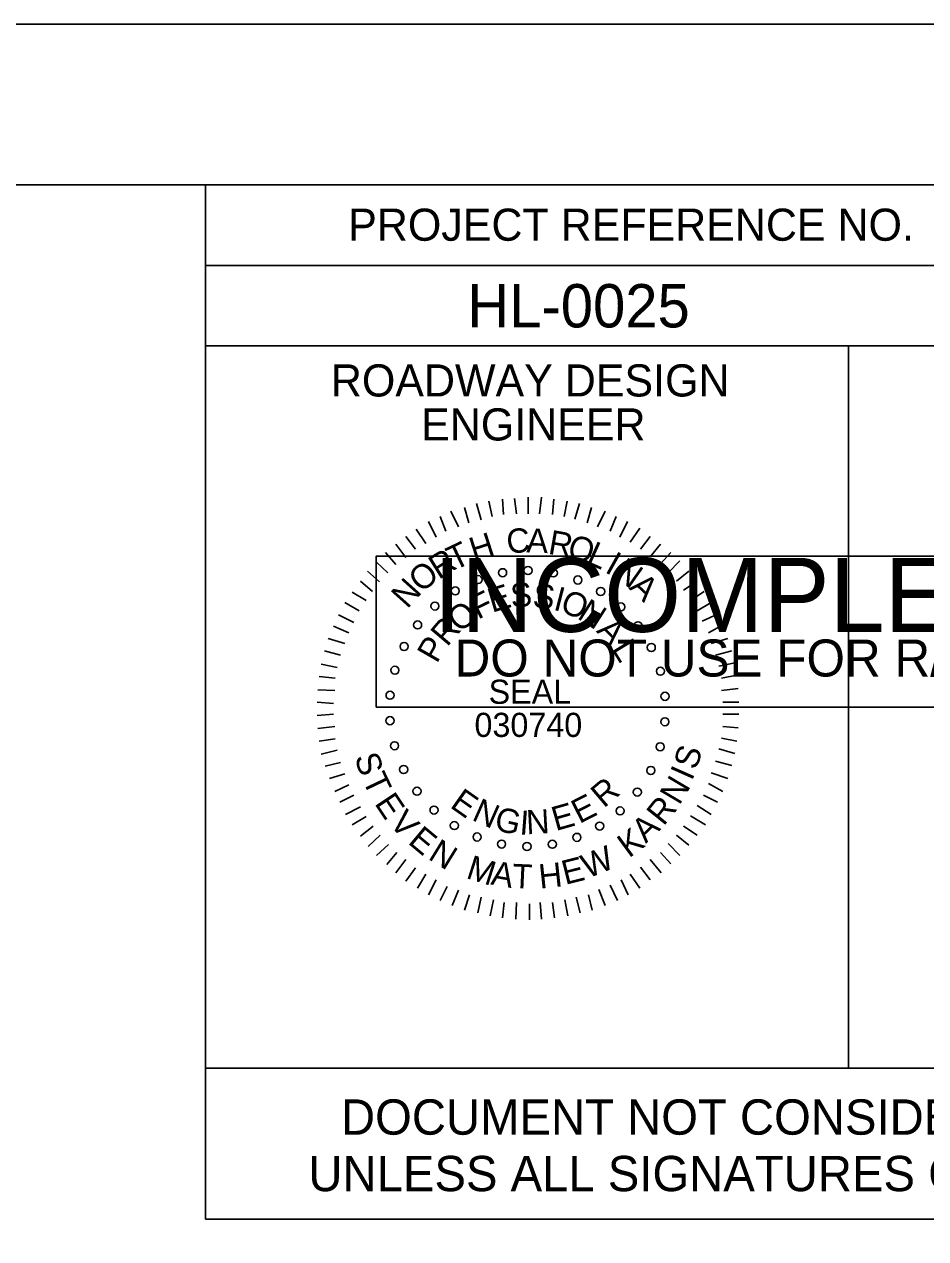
# Model space of a CAD drawing. Extents: x 1487909 to 1489267, y 497866 to 499814.
# Drawn here: x 1489027.14 to 1489041.17, y 497957.31 to 497976.22 of the extents above; entities that cross this region are included whole.
import ezdxf

# ---------------------------------------------------------------- set-up
doc = ezdxf.new("R2010")
doc.units = 0
for name, color, linetype in [('Old_Level_9', 7, 'Continuous'), ('Sheet Data Field CELL', 7, 'Continuous'), ('Sheet Plot Border Outside CELL', 7, 'Continuous'), ('Sheet Sticker Exception Certification CELL', 7, 'Continuous'), ('Sheet Sticker Incomplete CELL', 7, 'Continuous'), ('Sheet Typical CELL', 7, 'Continuous')]:
    doc.layers.add(name, color=color, linetype=linetype)

msp = doc.modelspace()

# ---------------------------------------------------------------- linework, layer by layer
at = {"layer": 'Old_Level_9'}
for p, q in [((1489034.178, 497968.758), (1489034.248, 497968.508)), ((1489034.368, 497968.798), (1489034.418, 497968.558)), ((1489034.578, 497968.828), (1489034.598, 497968.588)), ((1489034.768, 497968.838), (1489034.798, 497968.598)), ((1489034.978, 497968.858), (1489034.978, 497968.598)), ((1489035.188, 497968.858), (1489035.158, 497968.598)), ((1489035.378, 497968.828), (1489035.358, 497968.588)), ((1489035.588, 497968.798), (1489035.538, 497968.558)), ((1489035.778, 497968.758), (1489035.708, 497968.518)), ((1489033.608, 497968.558), (1489033.698, 497968.328)), ((1489033.778, 497968.638), (1489033.898, 497968.398)), ((1489033.988, 497968.698), (1489034.058, 497968.458)), ((1489035.968, 497968.698), (1489035.898, 497968.458)), ((1489036.178, 497968.638), (1489036.058, 497968.398)), ((1489036.348, 497968.558), (1489036.258, 497968.328)), ((1489033.428, 497968.478), (1489033.548, 497968.238)), ((1489036.528, 497968.478), (1489036.408, 497968.238)), ((1489036.718, 497968.378), (1489036.568, 497968.158)), ((1489033.078, 497968.248), (1489033.228, 497968.048)), ((1489033.238, 497968.358), (1489033.388, 497968.138)), ((1489036.878, 497968.248), (1489036.728, 497968.048)), ((1489032.758, 497967.998), (1489032.918, 497967.808)), ((1489032.918, 497968.128), (1489033.078, 497967.918)), ((1489037.038, 497968.128), (1489036.878, 497967.928)), ((1489037.198, 497967.998), (1489037.038, 497967.818)), ((1489032.618, 497967.848), (1489032.798, 497967.678)), ((1489037.338, 497967.868), (1489037.158, 497967.678)), ((1489032.478, 497967.708), (1489032.668, 497967.538)), ((1489037.478, 497967.708), (1489037.288, 497967.548)), ((1489032.368, 497967.548), (1489032.558, 497967.388)), ((1489037.608, 497967.548), (1489037.398, 497967.408)), ((1489032.238, 497967.378), (1489032.458, 497967.248)), ((1489037.718, 497967.388), (1489037.508, 497967.248)), ((1489032.128, 497967.218), (1489032.348, 497967.088)), ((1489037.828, 497967.218), (1489037.608, 497967.088)), ((1489037.928, 497967.038), (1489037.688, 497966.928)), ((1489032.028, 497967.028), (1489032.268, 497966.908)), ((1489038.008, 497966.868), (1489037.788, 497966.748)), ((1489031.948, 497966.848), (1489032.188, 497966.748)), ((1489031.868, 497966.658), (1489032.128, 497966.578)), ((1489038.088, 497966.658), (1489037.828, 497966.578)), ((1489031.808, 497966.468), (1489032.058, 497966.398)), ((1489038.148, 497966.468), (1489037.898, 497966.398)), ((1489031.758, 497966.258), (1489032.008, 497966.208)), ((1489038.198, 497966.278), (1489037.948, 497966.228)), ((1489031.728, 497966.068), (1489031.978, 497966.038)), ((1489038.228, 497966.088), (1489037.988, 497966.038)), ((1489031.708, 497965.858), (1489031.968, 497965.848)), ((1489038.248, 497965.878), (1489037.988, 497965.848)), ((1489031.698, 497965.668), (1489031.948, 497965.648)), ((1489038.258, 497965.668), (1489038.008, 497965.668)), ((1489031.698, 497965.458), (1489031.948, 497965.478)), ((1489038.258, 497965.478), (1489038.008, 497965.478)), ((1489031.708, 497965.258), (1489031.968, 497965.288)), ((1489038.248, 497965.268), (1489038.008, 497965.288)), ((1489031.728, 497965.058), (1489031.978, 497965.098)), ((1489038.228, 497965.058), (1489037.988, 497965.108)), ((1489031.758, 497964.858), (1489032.008, 497964.918)), ((1489038.198, 497964.868), (1489037.948, 497964.938)), ((1489031.818, 497964.668), (1489032.058, 497964.728)), ((1489038.148, 497964.678), (1489037.898, 497964.748)), ((1489031.888, 497964.478), (1489032.128, 497964.548)), ((1489038.008, 497964.278), (1489037.788, 497964.398)), ((1489038.088, 497964.478), (1489037.828, 497964.568)), ((1489031.968, 497964.278), (1489032.188, 497964.378)), ((1489032.048, 497964.108), (1489032.268, 497964.218)), ((1489037.928, 497964.108), (1489037.708, 497964.218)), ((1489032.138, 497963.918), (1489032.368, 497964.038)), ((1489037.828, 497963.918), (1489037.608, 497964.058)), ((1489032.238, 497963.758), (1489032.458, 497963.888)), ((1489037.738, 497963.758), (1489037.508, 497963.898)), ((1489032.368, 497963.578), (1489032.568, 497963.738)), ((1489037.608, 497963.598), (1489037.398, 497963.738)), ((1489032.488, 497963.418), (1489032.678, 497963.598)), ((1489032.618, 497963.278), (1489032.808, 497963.448)), ((1489037.338, 497963.278), (1489037.158, 497963.468)), ((1489037.478, 497963.438), (1489037.288, 497963.598)), ((1489032.778, 497963.138), (1489032.938, 497963.328)), ((1489037.198, 497963.148), (1489037.038, 497963.328)), ((1489032.918, 497963.008), (1489033.078, 497963.218)), ((1489033.078, 497962.878), (1489033.228, 497963.088)), ((1489036.878, 497962.898), (1489036.728, 497963.098)), ((1489037.048, 497963.008), (1489036.878, 497963.218)), ((1489033.258, 497962.768), (1489033.388, 497962.988)), ((1489033.428, 497962.668), (1489033.548, 497962.898)), ((1489036.538, 497962.668), (1489036.428, 497962.898)), ((1489036.718, 497962.768), (1489036.568, 497962.988)), ((1489033.608, 497962.578), (1489033.718, 497962.798)), ((1489033.798, 497962.498), (1489033.898, 497962.738)), ((1489036.178, 497962.498), (1489036.078, 497962.748)), ((1489036.368, 497962.578), (1489036.258, 497962.818)), ((1489033.988, 497962.428), (1489034.068, 497962.668)), ((1489034.198, 497962.388), (1489034.248, 497962.628)), ((1489034.388, 497962.338), (1489034.438, 497962.588)), ((1489034.578, 497962.308), (1489034.608, 497962.548)), ((1489034.788, 497962.288), (1489034.798, 497962.548)), ((1489034.998, 497962.278), (1489034.998, 497962.528)), ((1489035.188, 497962.288), (1489035.168, 497962.548)), ((1489035.388, 497962.308), (1489035.358, 497962.548)), ((1489035.598, 497962.338), (1489035.548, 497962.588)), ((1489035.788, 497962.388), (1489035.728, 497962.628)), ((1489035.978, 497962.428), (1489035.918, 497962.668))]:
    msp.add_line(p, q, dxfattribs=at)
for centre in [(1489034.201, 497967.575), (1489034.582, 497967.682), (1489034.977, 497967.717), (1489035.372, 497967.679), (1489035.753, 497967.569), (1489033.845, 497967.399), (1489036.108, 497967.39), (1489033.528, 497967.162), (1489036.423, 497967.15), (1489033.259, 497966.869), (1489036.689, 497966.856), (1489033.049, 497966.533), (1489036.896, 497966.518), (1489032.905, 497966.164), (1489037.038, 497966.148), (1489032.83, 497965.774), (1489037.11, 497965.758), (1489032.829, 497965.378), (1489037.108, 497965.361), (1489032.9, 497964.988), (1489037.034, 497964.972), (1489033.042, 497964.618), (1489036.889, 497964.603), (1489033.249, 497964.28), (1489036.679, 497964.266), (1489033.515, 497963.986), (1489036.411, 497963.974), (1489033.831, 497963.745), (1489036.093, 497963.737), (1489034.185, 497963.567), (1489034.566, 497963.457), (1489034.961, 497963.419), (1489035.356, 497963.454), (1489035.738, 497963.561)]:
    msp.add_circle(centre, 0.063, dxfattribs=at)
at = {"layer": 'Sheet Plot Border Outside CELL'}
msp.add_lwpolyline([(1489051.664, 497976.221), (1488883.264, 497976.221), (1488883.264, 497866.221), (1489051.664, 497866.221)], close=True, dxfattribs=at)
at = {"layer": 'Sheet Sticker Exception Certification CELL'}
for p, q in [((1489029.959, 497957.616), (1489029.959, 497959.966)), ((1489029.959, 497959.966), (1489049.962, 497959.966)), ((1489049.962, 497957.616), (1489029.959, 497957.616))]:
    msp.add_line(p, q, dxfattribs=at)
at = {"layer": 'Sheet Sticker Incomplete CELL'}
msp.add_lwpolyline([(1489032.614, 497965.591), (1489032.614, 497967.941), (1489047.314, 497967.941), (1489047.314, 497965.591)], close=True, dxfattribs=at)
at = {"layer": 'Sheet Typical CELL'}
for p, q in [((1489029.959, 497972.466), (1489049.964, 497972.466)), ((1489039.964, 497971.216), (1489039.964, 497959.971))]:
    msp.add_line(p, q, dxfattribs=at)
for points in [[(1489049.964, 497973.721), (1488899.964, 497973.721), (1488899.964, 497868.721), (1489049.964, 497868.721)], [(1489029.959, 497973.721), (1489049.964, 497973.721), (1489049.964, 497971.216), (1489029.959, 497971.216)], [(1489029.959, 497971.216), (1489039.964, 497971.216), (1489039.964, 497959.966), (1489029.959, 497959.966)], [(1489039.964, 497971.216), (1489049.964, 497971.216), (1489049.964, 497959.966), (1489039.964, 497959.966)]]:
    msp.add_lwpolyline(points, close=True, dxfattribs=at)

# ---------------------------------------------------------------- texts
at = {"layer": 'Old_Level_9'}
for s, height, rotation, p in [('C', 0.378, 4.9399, (1489034.658, 497967.978)), ('A', 0.378, 357.9749, (1489034.948, 497967.998)), ('T', 0.378, 25.4358, (1489033.828, 497967.708)), ('H', 0.378, 17.7433, (1489034.138, 497967.848)), ('R', 0.378, 350.0216, (1489035.278, 497967.978)), ('O', 0.378, 343.0868, (1489035.568, 497967.928)), ('R', 0.378, 32.1754, (1489033.588, 497967.568)), ('L', 0.378, 335.7459, (1489035.868, 497967.838)), ('I', 0.378, 330.806, (1489036.158, 497967.698)), ('O', 0.378, 39.9442, (1489033.318, 497967.358)), ('N', 0.378, 324.9038, (1489036.288, 497967.628)), ('A', 0.378, 317.0051, (1489036.538, 497967.438)), ('N', 0.378, 48.0667, (1489033.098, 497967.108)), ('E', 0.376, 16.5889, (1489034.418, 497967.058)), ('S', 0.376, 4.468, (1489034.718, 497967.138)), ('S', 0.376, 353.0415, (1489035.038, 497967.148)), ('I', 0.376, 345.4821, (1489035.358, 497967.108)), ('F', 0.376, 26.4, (1489034.198, 497966.948)), ('O', 0.376, 337.8749, (1489035.458, 497967.088)), ('N', 0.376, 327.393, (1489035.728, 497966.978)), ('O', 0.376, 38.2518, (1489033.908, 497966.738)), ('R', 0.376, 49.7478, (1489033.718, 497966.518)), ('A', 0.376, 313.9438, (1489036.028, 497966.768)), ('P', 0.376, 60.1236, (1489033.558, 497966.258)), ('L', 0.376, 301.5323, (1489036.268, 497966.498)), ('S', 0.378, 72.2579, (1489037.596, 497964.599)), ('S', 0.378, 288.212, (1489032.273, 497964.81)), ('T', 0.378, 295.6244, (1489032.392, 497964.458)), ('I', 0.378, 66.0464, (1489037.526, 497964.43)), ('R', 0.376, 40.3493, (1489036.158, 497964.008)), ('N', 0.378, 59.3726, (1489037.333, 497964.05)), ('E', 0.378, 303.8225, (1489032.579, 497964.09)), ('E', 0.376, 324.8692, (1489033.748, 497964.038)), ('E', 0.376, 27.1568, (1489035.778, 497963.768)), ('V', 0.378, 311.9298, (1489032.805, 497963.772)), ('N', 0.376, 336.0584, (1489034.088, 497963.838)), ('G', 0.376, 347.4812, (1489034.438, 497963.678)), ('E', 0.376, 15.8057, (1489035.408, 497963.658)), ('R', 0.378, 51.1503, (1489037.087, 497963.726)), ('I', 0.376, 355.6246, (1489034.838, 497963.608)), ('N', 0.376, 3.1278, (1489034.958, 497963.608)), ('A', 0.378, 43.5217, (1489036.811, 497963.459)), ('E', 0.378, 320.2312, (1489033.094, 497963.475)), ('K', 0.378, 36.141, (1489036.548, 497963.232)), ('N', 0.378, 328.329, (1489033.407, 497963.232)), ('M', 0.378, 342.337, (1489033.998, 497962.932)), ('E', 0.378, 14.1648, (1489035.557, 497962.82)), ('W', 0.378, 22.0058, (1489035.903, 497962.916)), ('A', 0.378, 350.1822, (1489034.387, 497962.829)), ('T', 0.378, 357.3866, (1489034.728, 497962.773)), ('H', 0.378, 6.0112, (1489035.163, 497962.762))]:
    msp.add_text(s, height=height, rotation=rotation, dxfattribs=at).set_placement(p)
for s, p in [('SEAL', (1489034.364, 497965.641)), ('030740', (1489034.144, 497965.125))]:
    msp.add_text(s, height=0.3759, dxfattribs=at).set_placement(p)
at = {"layer": 'Sheet Data Field CELL'}
msp.add_text('HL-0025', height=0.675, dxfattribs=at).set_placement((1489034.033, 497971.501))
at = {"layer": 'Sheet Sticker Exception Certification CELL'}
for s, p in [('DOCUMENT NOT CONSIDERED FINAL', (1489032.066, 497958.932)), ('UNLESS ALL SIGNATURES COMPLETED', (1489031.559, 497958.052))]:
    msp.add_text(s, height=0.55, dxfattribs=at).set_placement(p)
at = {"layer": 'Sheet Sticker Incomplete CELL'}
for s, height, p in [('INCOMPLETE PLANS', 1.152, (1489033.509, 497966.761)), ('DO NOT USE FOR R/W ACQUISITION', 0.576, (1489033.834, 497966.066))]:
    msp.add_text(s, height=height, dxfattribs=at).set_placement(p)
at = {"layer": 'Sheet Typical CELL'}
for s, height, p in [('PROJECT REFERENCE NO.', 0.50001, (1489032.179, 497972.851)), ('ROADWAY DESIGN', 0.50001, (1489031.909, 497970.426)), ('ENGINEER', 0.5, (1489033.314, 497969.741))]:
    msp.add_text(s, height=height, dxfattribs=at).set_placement(p)

doc.saveas('drawing.dxf')
